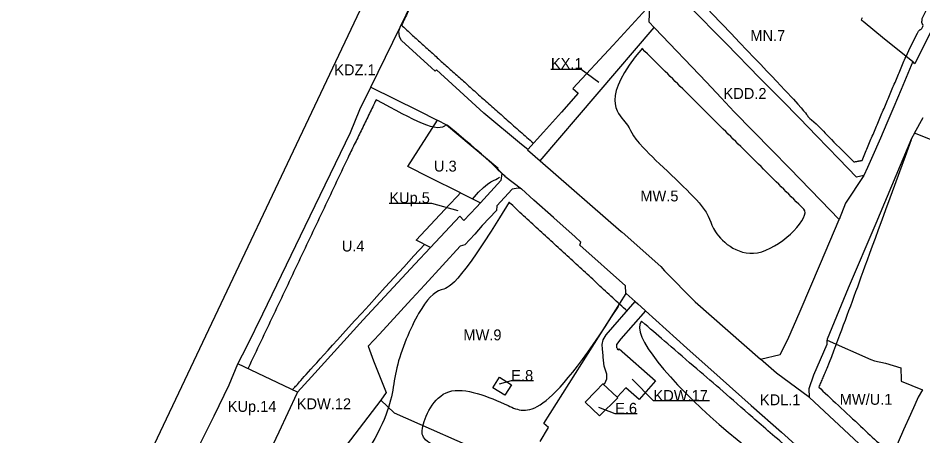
# Model space of a CAD drawing. Extents: x 7424788 to 7425732, y 5549810 to 5550591.
# Drawn here: x 7424904.1 to 7425235.6, y 5550031.4 to 5550184.4 of the extents above; entities that cross this region are included whole.
import ezdxf

# ---------------------------------------------------------------- set-up
doc = ezdxf.new("R2010")
doc.units = 0
for name, color, linetype in [('WIL_granica obszaru objętego planem', 7, 'Continuous'), ('WIL_linia rozgraniczające tereny o różnym przeznaczeniu lub różnych zasadach zagospodarowania', 7, 'Continuous'), ('WIL_linia rozgraniczające tereny o różnym przeznaczeniu lub różnych zasadach zagospodarowania_OPISY', 7, 'Continuous'), ('WIL_nieprzekraczalne linie zabudowy', 7, 'Continuous')]:
    doc.layers.add(name, color=color, linetype=linetype)

msp = doc.modelspace()

# ---------------------------------------------------------------- linework, layer by layer
at = {"layer": 'WIL_granica obszaru objętego planem'}
msp.add_line((7424904.13, 5549923.06), (7425177.26, 5550499.06), dxfattribs=at)
at = {"layer": 'WIL_linia rozgraniczające tereny o różnym przeznaczeniu lub różnych zasadach zagospodarowania'}
for p, q in [((7424904.13, 5549923.06), (7425177.26, 5550499.06)), ((7425044.09, 5550181.16), (7425048.44, 5550189.85)), ((7425135.52, 5550189.18), (7425122.11, 5550174.46)), ((7425135.34, 5550182.92), (7425135.52, 5550189.18)), ((7425163.53, 5550175.09), (7425149.73, 5550189.09)), ((7425137.22, 5550180.96), (7425135.34, 5550182.92)), ((7425213.33, 5550184.48), (7425213, 5550183.82)), ((7425213, 5550183.82), (7425213.74, 5550183.36)), ((7425213.74, 5550183.36), (7425217.95, 5550179.8)), ((7425240.93, 5550184.38), (7425232.72, 5550167.74)), ((7425033.35, 5550159.11), (7425044.09, 5550181.16)), ((7425043.59, 5550179.67), (7425044.09, 5550181.16)), ((7425043.82, 5550177.53), (7425043.59, 5550179.67)), ((7425095.34, 5550132.22), (7425137.22, 5550180.96)), ((7425137.39, 5550180.78), (7425137.22, 5550180.96)), ((7425156.38, 5550160.96), (7425137.39, 5550180.78)), ((7425217.95, 5550179.8), (7425220.78, 5550177.4)), ((7425044.56, 5550176.2), (7425043.82, 5550177.53)), ((7425055.61, 5550166.17), (7425044.56, 5550176.2)), ((7425220.78, 5550177.4), (7425231.89, 5550168.48)), ((7425122.11, 5550174.46), (7425107.37, 5550158.68)), ((7425175.92, 5550162.49), (7425163.53, 5550175.09)), ((7425056.93, 5550165), (7425055.61, 5550166.17)), ((7425057.4, 5550165.43), (7425056.93, 5550165)), ((7425067.38, 5550156.29), (7425057.4, 5550165.43)), ((7425231.89, 5550168.48), (7425227.64, 5550158.27)), ((7425232.72, 5550167.74), (7425231.89, 5550168.48)), ((7425179.93, 5550158.41), (7425175.92, 5550162.49)), ((7425029.3, 5550150.96), (7425033.35, 5550159.11)), ((7425033.35, 5550159.11), (7425050.69, 5550150.59)), ((7425107.37, 5550158.68), (7425109.37, 5550156.96)), ((7425161.73, 5550155.26), (7425156.38, 5550160.96)), ((7425074.73, 5550149.62), (7425067.38, 5550156.29)), ((7425109.37, 5550156.96), (7425103.16, 5550150.04)), ((7425183.82, 5550154.45), (7425179.93, 5550158.41)), ((7425227.64, 5550158.27), (7425224.92, 5550151.92)), ((7425166.52, 5550150.16), (7425161.73, 5550155.26)), ((7425190.37, 5550147.8), (7425183.82, 5550154.45)), ((7425025.94, 5550142.58), (7425029.3, 5550150.96)), ((7425050.69, 5550150.59), (7425057.64, 5550147.07)), ((7425088.5, 5550138.15), (7425074.73, 5550149.62)), ((7425103.16, 5550150.04), (7425096.58, 5550142.72)), ((7425180.22, 5550136.1), (7425166.52, 5550150.16)), ((7425224.92, 5550151.92), (7425222.44, 5550145.99)), ((7425046.9, 5550130.1), (7425057.75, 5550147.02)), ((7425057.64, 5550147.07), (7425057.75, 5550147.02)), ((7425057.75, 5550147.02), (7425061.13, 5550145.3)), ((7425196.77, 5550141.23), (7425190.37, 5550147.8)), ((7425222.44, 5550145.99), (7425220.09, 5550140.5)), ((7425232.57, 5550142.3), (7425235.74, 5550148.06)), ((7425009.33, 5550108.23), (7425025.94, 5550142.58)), ((7425061.13, 5550145.3), (7425079.93, 5550129.66)), ((7425096.58, 5550142.72), (7425090.82, 5550136.3)), ((7425232.57, 5550142.3), (7425231.48, 5550140.31)), ((7425248.67, 5550135.84), (7425232.57, 5550142.3)), ((7425204.78, 5550132.9), (7425196.77, 5550141.23)), ((7425220.09, 5550140.5), (7425216.74, 5550132.98)), ((7425231.48, 5550140.31), (7425218.32, 5550109.18)), ((7425090.82, 5550136.3), (7425088.5, 5550138.15)), ((7425090.82, 5550136.3), (7425090.75, 5550136.22)), ((7425090.75, 5550136.22), (7425095.34, 5550132.22)), ((7425186.69, 5550129.52), (7425180.22, 5550136.1)), ((7425095.34, 5550132.22), (7425125.07, 5550106.29)), ((7425211.29, 5550126.19), (7425204.78, 5550132.9)), ((7425216.74, 5550132.98), (7425215.32, 5550129.77)), ((7425054.81, 5550126.1), (7425046.9, 5550130.1)), ((7425079.93, 5550129.66), (7425079.6, 5550129.09)), ((7425079.6, 5550129.09), (7425081.31, 5550127.53)), ((7425198.24, 5550117.67), (7425186.69, 5550129.52)), ((7425215.32, 5550129.77), (7425213.96, 5550126.82)), ((7425066.18, 5550120.47), (7425054.81, 5550126.1)), ((7425081.31, 5550127.53), (7425081.04, 5550124.96)), ((7425081.31, 5550127.53), (7425081.32, 5550127.52)), ((7425081.32, 5550127.52), (7425082.45, 5550126.49)), ((7425082.45, 5550126.49), (7425088.52, 5550121.86)), ((7425213.96, 5550126.82), (7425207.28, 5550116.61)), ((7425213.96, 5550126.82), (7425211.29, 5550126.19)), ((7425081.04, 5550124.96), (7425073.53, 5550116.82)), ((7425062.19, 5550116.23), (7425064.99, 5550119.14)), ((7425064.99, 5550119.14), (7425066.18, 5550120.47)), ((7425066.18, 5550120.47), (7425073.53, 5550116.82)), ((7425085.18, 5550121.78), (7425079.54, 5550115.68)), ((7425087.3, 5550122.15), (7425085.18, 5550121.78)), ((7425088.52, 5550121.86), (7425087.3, 5550122.15)), ((7425093.12, 5550117.78), (7425088.52, 5550121.86)), ((7425049.99, 5550103.13), (7425062.19, 5550116.23)), ((7425073.53, 5550116.82), (7425072.03, 5550115.22)), ((7425079.54, 5550115.68), (7425079.36, 5550113.97)), ((7425100.28, 5550111.43), (7425093.12, 5550117.78)), ((7425205, 5550110.73), (7425198.24, 5550117.67)), ((7425207.28, 5550116.61), (7425205, 5550110.73)), ((7425072.03, 5550115.22), (7425067.49, 5550110.37)), ((7425079.36, 5550113.97), (7425074.19, 5550108.43)), ((7425065.91, 5550111.9), (7425055.23, 5550100.42)), ((7425067.49, 5550110.37), (7425065.91, 5550111.9)), ((7425100.57, 5550111.17), (7425100.28, 5550111.43)), ((7425105.86, 5550106.43), (7425100.57, 5550111.17)), ((7425198.14, 5550094.57), (7425205, 5550110.73)), ((7425218.32, 5550109.18), (7425208.2, 5550085.55)), ((7424993.82, 5550076.14), (7425009.33, 5550108.23)), ((7425074.19, 5550108.43), (7425071.5, 5550105.32)), ((7425108.19, 5550104.33), (7425105.86, 5550106.43)), ((7425125.07, 5550106.29), (7425125.36, 5550106.05)), ((7425125.36, 5550106.05), (7425125.39, 5550106.03)), ((7425125.39, 5550106.03), (7425139.66, 5550093.42)), ((7425055.23, 5550100.42), (7425049.99, 5550103.13)), ((7425071.5, 5550105.32), (7425067.85, 5550101.35)), ((7425108.23, 5550104.3), (7425108.19, 5550104.33)), ((7425110.3, 5550102.44), (7425108.23, 5550104.3)), ((7425109.97, 5550101.32), (7425110.3, 5550102.44)), ((7425055.23, 5550100.42), (7425049.54, 5550094.3)), ((7425066.13, 5550100.93), (7425053.13, 5550086.82)), ((7425067.85, 5550101.35), (7425066.13, 5550100.93)), ((7425126.69, 5550086.42), (7425109.97, 5550101.32)), ((7425049.54, 5550094.3), (7425030.55, 5550073.97)), ((7425139.66, 5550093.42), (7425140.98, 5550091.86)), ((7425190.62, 5550077.1), (7425198.14, 5550094.57)), ((7425140.98, 5550091.86), (7425152.16, 5550080.58)), ((7425053.13, 5550086.82), (7425048.42, 5550081.69)), ((7425126.73, 5550083.79), (7425126.69, 5550086.42)), ((7425096.71, 5550036.04), (7425126.93, 5550083.61)), ((7425126.77, 5550083.75), (7425126.73, 5550083.79)), ((7425126.93, 5550083.61), (7425126.77, 5550083.75)), ((7425126.93, 5550083.61), (7425126.96, 5550083.58)), ((7425126.96, 5550083.58), (7425130.22, 5550080.62)), ((7425208.2, 5550085.55), (7425200.51, 5550066.9)), ((7425048.2, 5550081.46), (7425036.5, 5550068.73)), ((7425048.42, 5550081.69), (7425048.2, 5550081.46)), ((7425119.55, 5550068.4), (7425130.22, 5550080.62)), ((7425130.22, 5550080.62), (7425131.13, 5550079.8)), ((7425131.13, 5550079.8), (7425133.73, 5550077.44)), ((7425152.16, 5550080.58), (7425176.08, 5550059.6)), ((7424988, 5550064.48), (7424993.82, 5550076.14)), ((7425133.94, 5550077.26), (7425125.01, 5550066.96)), ((7425133.73, 5550077.44), (7425133.94, 5550077.26)), ((7425133.94, 5550077.26), (7425149.19, 5550063.56)), ((7425186.15, 5550066.72), (7425190.62, 5550077.1)), ((7425030.55, 5550073.97), (7425011.57, 5550053.01)), ((7425036.5, 5550068.73), (7425032.44, 5550064.26)), ((7425118.12, 5550064.94), (7425118.54, 5550066.67)), ((7425118.54, 5550066.67), (7425119.55, 5550068.4)), ((7425125.01, 5550066.96), (7425123.35, 5550064.96)), ((7425183.35, 5550061.23), (7425186.15, 5550066.72)), ((7425200.5, 5550065.09), (7425200.51, 5550066.44)), ((7425200.51, 5550066.9), (7425200.51, 5550066.44)), ((7425200.51, 5550066.44), (7425216.5, 5550059.45)), ((7424984.68, 5550057.85), (7424988, 5550064.48)), ((7425032.44, 5550064.26), (7425034.39, 5550058.92)), ((7425118.18, 5550063.21), (7425118.12, 5550064.94)), ((7425118.52, 5550060.83), (7425118.18, 5550063.21)), ((7425123.35, 5550064.96), (7425123.35, 5550063.81)), ((7425123.35, 5550063.81), (7425123.72, 5550063.44)), ((7425123.72, 5550063.44), (7425123.63, 5550063.34)), ((7425123.63, 5550063.34), (7425124.07, 5550062.95)), ((7425124.07, 5550062.95), (7425124.36, 5550063.28)), ((7425124.36, 5550063.28), (7425137.67, 5550051.55)), ((7425149.19, 5550063.56), (7425161.3, 5550052.69)), ((7425195.7, 5550053.82), (7425200.5, 5550065.09)), ((7425118.5, 5550060.32), (7425118.52, 5550060.83)), ((7425118.88, 5550056.99), (7425118.5, 5550060.32)), ((7425176.08, 5550059.6), (7425183.35, 5550061.23)), ((7425182.02, 5550054.39), (7425176.08, 5550059.6)), ((7425216.5, 5550059.45), (7425217.84, 5550058.87)), ((7424981.48, 5550050.13), (7424984.66, 5550057.82)), ((7424984.66, 5550057.82), (7424984.68, 5550057.85)), ((7425006.55, 5550047.47), (7424984.68, 5550057.85)), ((7425034.39, 5550058.92), (7425039, 5550047.36)), ((7425119.79, 5550054.07), (7425118.88, 5550056.99)), ((7425217.84, 5550058.87), (7425221.93, 5550058.09)), ((7425221.93, 5550058.09), (7425227.55, 5550056.31)), ((7425227.55, 5550056.31), (7425227.6, 5550051.92)), ((7425011.57, 5550053.01), (7425006.55, 5550047.47)), ((7425078.03, 5550049.04), (7425080.46, 5550052.95)), ((7425080.46, 5550052.95), (7425084.87, 5550050.2)), ((7425119.79, 5550052.29), (7425119.79, 5550054.07)), ((7425161.3, 5550052.69), (7425172.67, 5550042.53)), ((7425194.11, 5550045.49), (7425182.02, 5550054.39)), ((7425193.97, 5550048.77), (7425195.7, 5550053.82)), ((7424975.91, 5550038.84), (7424981.48, 5550050.13)), ((7425084.87, 5550050.2), (7425082.45, 5550046.3)), ((7425115.84, 5550047.87), (7425118.37, 5550050.47)), ((7425118.37, 5550050.47), (7425119.11, 5550050.63)), ((7425118.37, 5550050.47), (7425123.55, 5550045.67)), ((7425119.11, 5550050.63), (7425119.79, 5550052.29)), ((7425137.67, 5550051.55), (7425131.66, 5550044.73)), ((7425227.6, 5550051.92), (7425227.6, 5550051.51)), ((7425227.6, 5550051.51), (7425235.5, 5550048.3)), ((7425006.3, 5550046.98), (7424999.62, 5550032.75)), ((7425006.33, 5550047.05), (7425006.3, 5550046.98)), ((7425006.55, 5550047.47), (7425006.33, 5550047.05)), ((7425039, 5550047.36), (7425037.02, 5550044.53)), ((7425082.45, 5550046.3), (7425078.03, 5550049.04)), ((7425111.91, 5550043.84), (7425115.84, 5550047.87)), ((7425126.79, 5550049.08), (7425123.55, 5550045.67)), ((7425131.66, 5550044.73), (7425126.79, 5550049.08)), ((7425194.11, 5550045.49), (7425193.97, 5550048.77)), ((7425235.5, 5550048.3), (7425233.84, 5550045.61)), ((7425037.02, 5550044.53), (7425015.64, 5550016.61)), ((7425037.02, 5550044.53), (7425041.96, 5550039.92)), ((7425117.16, 5550038.73), (7425111.91, 5550043.84)), ((7425123.82, 5550045.42), (7425117.16, 5550038.73)), ((7425123.55, 5550045.67), (7425123.82, 5550045.42)), ((7425212.17, 5550028.66), (7425194.11, 5550045.49)), ((7425232.63, 5550042.87), (7425231.04, 5550039.27)), ((7425233.84, 5550045.61), (7425232.63, 5550042.87)), ((7425041.96, 5550039.92), (7425089.34, 5550019)), ((7425172.67, 5550042.53), (7425183.81, 5550032.81)), ((7424970.95, 5550028.81), (7424975.91, 5550038.84)), ((7425098.4, 5550034.5), (7425096.71, 5550036.04)), ((7425231.04, 5550039.27), (7425228.57, 5550033.67)), ((7424999.62, 5550032.75), (7424992.99, 5550018.64)), ((7425095.42, 5550029.4), (7425098.4, 5550034.5)), ((7425183.81, 5550032.81), (7425194.4, 5550023.28)), ((7425228.57, 5550033.67), (7425223.07, 5550021.22))]:
    msp.add_line(p, q, dxfattribs=at)
at = {"layer": 'WIL_linia rozgraniczające tereny o różnym przeznaczeniu lub różnych zasadach zagospodarowania_OPISY'}
for points in [[(7425099.35, 5550165.79), (7425110.44, 5550165.79), (7425116.91, 5550160.99)], [(7425040.13, 5550116.66), (7425055.56, 5550116.66), (7425065.28, 5550113.95)], [(7425092.95, 5550051.56), (7425084.81, 5550051.56), (7425080.34, 5550050.43)], [(7425157.49, 5550044.23), (7425136.93, 5550044.23), (7425129.14, 5550052.18)], [(7425130.99, 5550039.54), (7425122.86, 5550039.54), (7425116.85, 5550041.81)]]:
    msp.add_lwpolyline(points, dxfattribs=at)
at = {"layer": 'WIL_nieprzekraczalne linie zabudowy'}
for points, degree in [([(7425063.48, 5550221.69), (7425044.62, 5550181.81)], 1), ([(7425229.43, 5550170.39), (7425234.03, 5550180.16), (7425234.68, 5550180.2), (7425234.98, 5550180.28), (7425235.75, 5550181.41), (7425235.7, 5550182.14), (7425235, 5550182.73), (7425235.55, 5550183.56), (7425234.96, 5550184.24), (7425236.88, 5550186.76), (7425240.12, 5550196.02)], 3), ([(7425150.13, 5550194.84), (7425173.71, 5550169.9), (7425192.97, 5550150.03), (7425193.22, 5550148.26), (7425196.28, 5550146.1), (7425200.58, 5550141.39), (7425206.26, 5550135.89), (7425210.31, 5550131.77)], 3), ([(7425044.62, 5550181.81), (7425061.81, 5550166), (7425092.94, 5550138.6)], 2), ([(7425132.88, 5550173.44), (7425117.29, 5550155.46), (7425130.12, 5550144.02), (7425127.4, 5550141.19), (7425159.6, 5550112.77), (7425155.91, 5550108.32), (7425174.69, 5550090.62), (7425194.67, 5550111.88), (7425192.02, 5550114.43)], 3), ([(7425192.02, 5550114.43), (7425132.88, 5550173.17)], 1), ([(7425213.31, 5550132.32), (7425229.43, 5550170.39)], 1), ([(7425035.3, 5550154.5), (7425025.47, 5550134.33)], 1), ([(7425035.3, 5550154.5), (7425035.29, 5550154.51)], 1), ([(7425060.92, 5550145.47), (7425058.17, 5550141.84), (7425049.24, 5550147.05), (7425035.3, 5550154.5)], 3), ([(7425082.52, 5550126.6), (7425079.59, 5550129.09), (7425080.03, 5550129.75), (7425061.29, 5550145.28)], 3), ([(7425231.35, 5550139.81), (7425218.88, 5550105.97), (7425211.26, 5550084.88), (7425205.03, 5550068.06), (7425200.41, 5550056.1)], 3), ([(7425025.47, 5550134.33), (7424988.42, 5550056.25)], 1), ([(7425210.31, 5550131.77), (7425213.31, 5550132.32)], 1), ([(7425070.66, 5550118.17), (7425077.06, 5550125.9), (7425078.83, 5550124.47), (7425080.45, 5550126.24)], 3), ([(7425084, 5550116.97), (7425064.39, 5550084.82), (7425059.12, 5550086.67), (7425051.28, 5550078.98), (7425041.03, 5550054.98), (7425041.88, 5550039.52), (7425016.38, 5550001.91), (7425010.97, 5549988.95), (7425023.53, 5549982.92), (7425032.48, 5549978.98), (7425046.3, 5550008.75), (7425046.87, 5550009.18), (7425051.43, 5550006.76), (7425080.91, 5549993.79), (7425114.24, 5549978.91), (7425118.94, 5549976.91), (7425119.45, 5549978.1), (7425161.39, 5549959.96), (7425169.94, 5549978.62), (7425122.22, 5550000.85), (7425121.22, 5549998.57), (7425055.13, 5550028.34), (7425049.86, 5550030.83), (7425059.26, 5550053.19), (7425084.9, 5550042.08), (7425096.96, 5550036.41), (7425124.07, 5550078.83)], 3), ([(7425084.66, 5550116.37), (7425084, 5550116.97)], 1), ([(7425127.29, 5550077.13), (7425084.66, 5550116.37)], 1), ([(7425004.84, 5550048.54), (7425007.19, 5550051.04), (7425009.59, 5550054.24), (7425053.1, 5550101.66)], 3), ([(7425132.48, 5550073.42), (7425123.93, 5550063.74), (7425193.39, 5550002.62), (7425203.07, 5550012.58)], 3), ([(7425203.07, 5550012.58), (7425195.36, 5550019.12), (7425184.47, 5550028.49), (7425171.34, 5550039.79), (7425160.93, 5550049.06), (7425152, 5550056.61), (7425139.95, 5550067.04), (7425135.9, 5550070.57), (7425132.48, 5550073.42)], 3), ([(7425200.41, 5550056.1), (7425197.48, 5550049.33)], 1), ([(7425197.48, 5550049.33), (7425201.22, 5550045.72), (7425214.43, 5550033.52), (7425224.47, 5550023.95), (7425243.95, 5550011.41), (7425259.92, 5550004.53), (7425266.6, 5550002.11)], 3)]:
    msp.add_open_spline(points, degree=degree, dxfattribs=at)

# ---------------------------------------------------------------- texts
at = {"layer": 'WIL_linia rozgraniczające tereny o różnym przeznaczeniu lub różnych zasadach zagospodarowania_OPISY'}
for s, p in [('MN.7', (7425172.4, 5550176.07)), ('KX.1', (7425099.35, 5550165.79)), ('KDZ.1', (7425019.96, 5550163.48)), ('KDD.2', (7425162.57, 5550154.83)), ('U.3', (7425056.49, 5550128.23)), ('KUp.5', (7425040.13, 5550116.66)), ('MW.5', (7425132.1, 5550117.3)), ('U.4', (7425022.72, 5550098.97)), ('MW.9', (7425067.27, 5550066.43)), ('E.8', (7425084.81, 5550051.56)), ('KDW.17', (7425136.93, 5550044.23)), ('KDL.1', (7425175.91, 5550042.66)), ('MW/U.1', (7425205.15, 5550042.84)), ('KUp.14', (7424980.93, 5550040.23)), ('KDW.12', (7425006.21, 5550041.19)), ('E.6', (7425122.86, 5550039.54))]:
    msp.add_text(s, height=4, dxfattribs=at).set_placement(p)

doc.saveas('drawing.dxf')
